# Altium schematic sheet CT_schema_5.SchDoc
size 368 x 336 mm
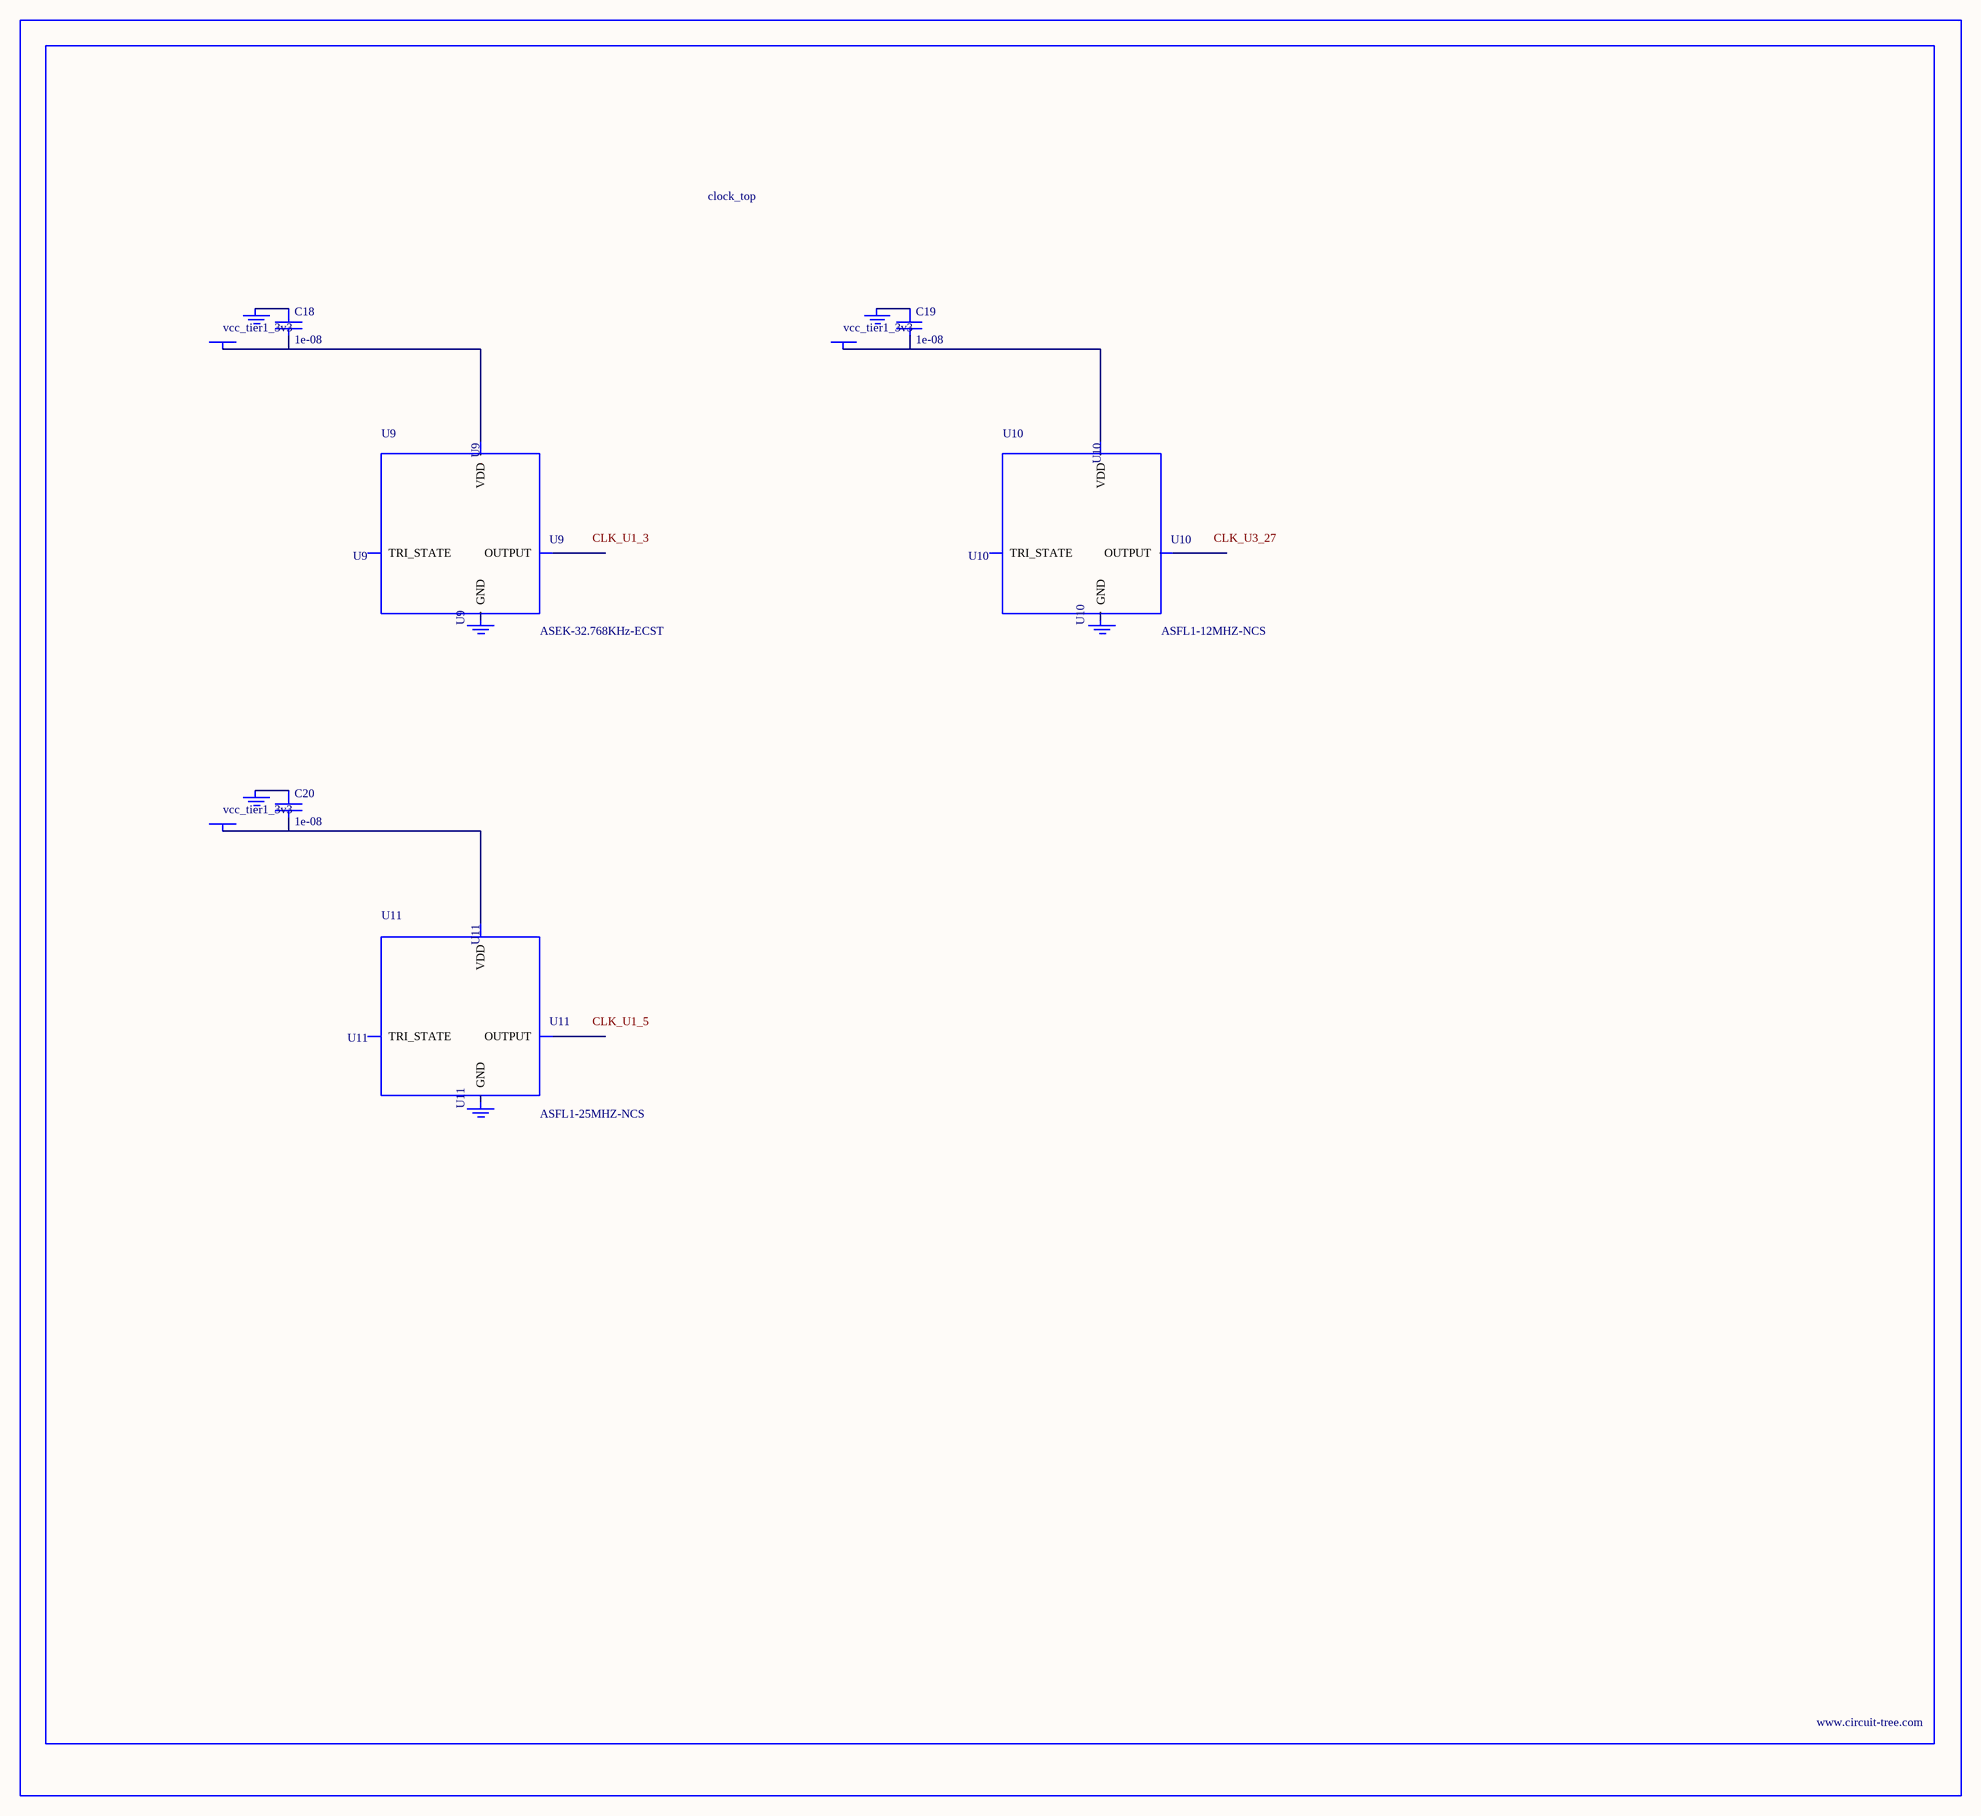
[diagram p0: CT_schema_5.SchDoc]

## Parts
BORDER4  (no value)
C18  1e-08  [C0402]
C19  1e-08  [C0402]
C20  1e-08  [C0402]
GND_INSTANCE_4_0  (no value)
GND_INSTANCE_4_1  (no value)
GND_INSTANCE_4_2  (no value)
GND_INSTANCE_4_3  (no value)
GND_INSTANCE_4_4  (no value)
GND_INSTANCE_4_5  (no value)
POWER_INSTANCE_4_0  vcc_tier1_3v3
POWER_INSTANCE_4_1  vcc_tier1_3v3
POWER_INSTANCE_4_2  vcc_tier1_3v3
U9  ASEK-32.768KHz-ECST  [ASEK]
U10  ASFL1-12MHZ-NCS  [ASFL1]
U11  ASFL1-25MHZ-NCS  [ASFL1]

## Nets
NetC18_1: C18.1 GND_INSTANCE_4_0.0(GND)
NetC18_2: C18.2 POWER_INSTANCE_4_0.0(PWR) U9.4(VDD)
NetC19_1: C19.1 GND_INSTANCE_4_2.0(GND)
NetC19_2: C19.2 POWER_INSTANCE_4_1.0(PWR) U10.4(VDD)
NetC20_1: C20.1 GND_INSTANCE_4_4.0(GND)
NetC20_2: C20.2 POWER_INSTANCE_4_2.0(PWR) U11.4(VDD)

Not connected (* = marked no-connect by the designer): GND_INSTANCE_4_1 0(GND); GND_INSTANCE_4_3 0(GND); GND_INSTANCE_4_5 0(GND); U9 1(TRI_STATE) 2(GND) 3(OUTPUT); U10 1(TRI_STATE) 2(GND) 3(OUTPUT); U11 1(TRI_STATE) 2(GND) 3(OUTPUT)

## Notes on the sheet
- Labels drawn without touching a wire or pin: CLK_U1_3, CLK_U1_5, CLK_U3_27

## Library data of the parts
BORDER4 = BORDER_PAGE4
C18-C20 = C0402C103K3RAC
GND_INSTANCE_4_0-GND_INSTANCE_4_5 = GND
POWER_INSTANCE_4_0-POWER_INSTANCE_4_2 = PWR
